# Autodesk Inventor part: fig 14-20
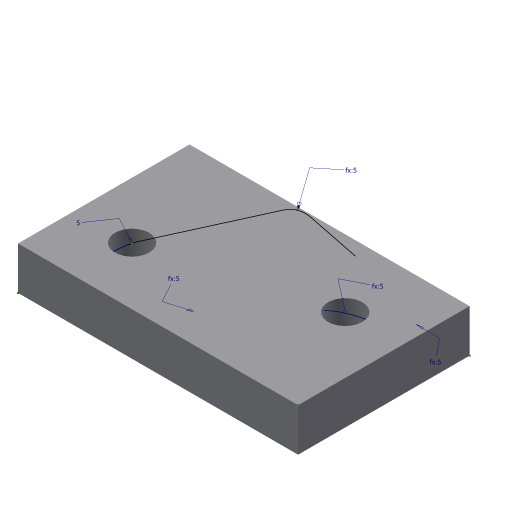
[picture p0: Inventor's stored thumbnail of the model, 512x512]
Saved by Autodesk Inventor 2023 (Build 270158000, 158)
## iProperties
Created: 2005-04
Part Number: fig 14-20
Document SubType Name: Modeling
Designer: CADCIM
Density: 1 g/cm^3
Material: Generic
Appearance: Default
Author: CADCIM
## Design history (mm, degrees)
sketch "Sketch1"
  geometry: L1 (-34.758, -22.218)-(30.545, -22.218); L2 (30.545, -22.218)-(30.545, 17.782); L3 (30.545, 17.782)-(-34.758, 17.782); L4 (-34.758, 17.782)-(-34.758, -22.218)
  constraints: 8 end point, 2 parallel, 1 horizontal, 1 perpendicular
  dimensions: "d0" = 65.30359 distance of L2.end L3.end; "d1" = 40 distance of L1.end L2.end
extrude "Extrusion1" new body sketch "Sketch1" distance "d2" = 10; taper "d3" = 0 deg
hole "Hole1" diameter "d13" = 8; stored, may be unused: countersink angle "d17" = 90 deg, drill point angle "d19" = 118 deg; dims "d11" = 13.458, "d12" = 13.14, "d14" = 6, "d15" = 4, "d16" = 2, "d18" = 15
hole "Hole2" diameter "d22" = 8; stored, may be unused: countersink angle "d26" = 90 deg, drill point angle "d28" = 118 deg; dims "d20" = 13.299, "d21" = 15.705, "d23" = 6, "d24" = 4, "d25" = 2, "d27" = 15
sketch "3D Sketch2" dims "d29" = 5, "d30" = 5 (= d29), "d31" = 5 (= d29), "d32" = 5 (= d29), "d33" = 5 (= d29)
body "Solid1"
other parameters: "LEN" = 1 [user parameter]
